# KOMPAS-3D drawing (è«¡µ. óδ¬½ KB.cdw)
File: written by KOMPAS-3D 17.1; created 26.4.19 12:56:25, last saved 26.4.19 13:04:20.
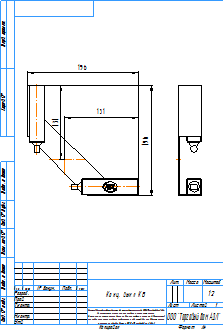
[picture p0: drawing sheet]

Sheet 1: A4, portrait

Title block, sheet 1: name: Конц. выкл KB; material: Сталь 20  ГОСТ 1050-88; sheets: 1; sheet format: A4

Views: Вид 1, Проекционный вид 2
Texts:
  kka
  adl
  Рама для чертежей
  Лит-Масса-Масштаб
  Материал-Предприятие
  Масштаб
  Изм.
  Лист
  № докум.
  Подп.
  Дата
  Лит.
  Разраб.
  Пров.
  Т.контр.
  Листов
  Внимание! Данный продукт является объектом авторского права ООО «Торговый Дом АДЛ».
  Запрещается изменение, копирование, распространение
  (в том числе путем копирования на другие сайты и ресурсы в Интернете)
  или любое иное использование информации и объектов без предварительного
  согласия правообладателя (ООО «Торговый Дом АДЛ»).
  Н.контр.
  Утв.
  ООО "Торговый дом АДЛ"
  Изменение
  Номер документа
  Подпись
  Обозначение документа
  Наименование изделия
  Масса изделия по ГОСТ 2.109-73
  Порядковый номер листа
  Общее количество листов в документе
  Характер работы, выполненной лицом, подписавшим документ
  Наименование или индекс предприятия, выпускающего документ
  Инв. № подл.
  Подп. и дата
  Взам. инв. №
  Инв. № дубл.
  Инвентарный номер подлинника по ГОСТ 2.501-68
  Подпись принявшего подлинник в отдел технической документации
  Инвентарный номер подлинника, взамен которого выпущен данный подлинник
  Инвентарный номер дубликата по ГОСТ 2.502-68
  Подпись принявшего дубликат в отдел технической документации
  Справ. №
  Перв. примен.
  Обозначение документа, взамен или на основании которого выпущен данный документ
  Обозначение документа, в котором впервые записан данный документ
  Подпись лица, копировавшего чертеж
  Обозначение формата листа
  !Рама для чертежа
Dimensions and other numbers on the sheet: 196; 131; 1:2; 1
